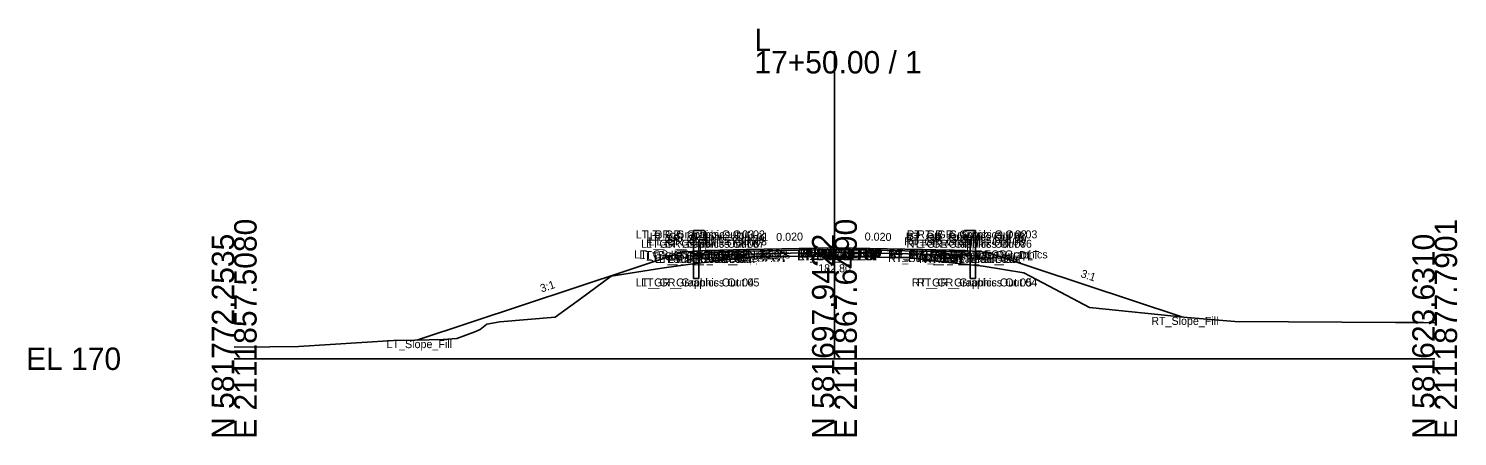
# Model space of a CAD drawing. Extents: x -26 to 3453, y -333 to 9539.
# Drawn here: x -25.7 to 152.8, y 7990.3 to 8041.2 of the extents above; entities that cross this region are included whole.
import ezdxf

# ---------------------------------------------------------------- set-up
doc = ezdxf.new("R2010")
doc.units = 0
for name, color, linetype in [('Default', 7, 'Continuous'), ('Exist Cross Section Cell', 7, 'Continuous'), ('Exist XS Center Line Elevation Label', 7, 'Continuous'), ('Exist XS Ground Line', 7, 'Continuous'), ('Prop CMT Guardrail Graphics', 7, 'Continuous'), ('Prop CMT Pvmt Course 1', 7, 'Continuous'), ('Prop CMT Pvmt Course 2', 7, 'Continuous'), ('Prop CMT Pvmt Course 3', 7, 'Continuous'), ('Prop CMT Pvmt Surface', 7, 'Continuous'), ('Prop CMT Pvmt Surface Shoulder', 7, 'Continuous'), ('Prop CMT Shld Paved Course 1', 7, 'Continuous'), ('Prop CMT Shld Paved Course 2', 7, 'Continuous'), ('Prop CMT Shld Paved Course 3', 7, 'Continuous'), ('Prop CMT Slope Grass', 7, 'Continuous'), ('Prop CMT Subgrade Earthwork', 7, 'Continuous'), ('Prop XS SE Text', 7, 'Continuous'), ('Prop XS Side Slope Text', 7, 'Continuous'), ('Scratch_Level_0', 7, 'Continuous')]:
    doc.layers.add(name, color=color, linetype=linetype)

msp = doc.modelspace()

# ---------------------------------------------------------------- linework, layer by layer
at = {"layer": 'Exist Cross Section Cell'}
for p, q in [((75, 8000), (75, 8038.42)), ((0, 8000), (75, 8000)), ((75, 8000), (150, 8000))]:
    msp.add_line(p, q, dxfattribs=at)
at = {"layer": 'Exist XS Ground Line'}
for p, q in [((57.32, 8011.85), (65.01, 8012.75)), ((65.01, 8012.75), (66.97, 8012.76)), ((66.97, 8012.76), (74.38, 8012.81)), ((74.38, 8012.81), (75, 8012.8)), ((75, 8012.8), (82.19, 8012.66)), ((82.19, 8012.66), (84.29, 8012.63)), ((84.29, 8012.63), (87.35, 8012.21)), ((47.12, 8010.31), (53.43, 8011.3)), ((53.43, 8011.3), (57.32, 8011.85)), ((87.35, 8012.21), (93.59, 8011.58)), ((93.59, 8011.58), (98.65, 8010.74)), ((43.29, 8007.49), (47.12, 8010.31)), ((98.65, 8010.74), (101.82, 8009.05)), ((101.82, 8009.05), (106.87, 8006.41)), ((40.11, 8005.18), (43.29, 8007.49)), ((106.87, 8006.41), (119.06, 8005.16)), ((30.08, 8003.35), (30.73, 8003.64)), ((30.73, 8003.64), (31.58, 8004.32)), ((31.58, 8004.32), (33.18, 8004.63)), ((33.18, 8004.63), (40.11, 8005.18)), ((119.06, 8005.16), (125.03, 8004.66)), ((125.03, 8004.66), (145.1, 8004.52)), ((145.1, 8004.52), (148.61, 8004.51)), ((148.61, 8004.51), (150, 8004.48)), ((8.04, 8001.53), (19.92, 8002.27)), ((19.92, 8002.27), (22.59, 8002.33)), ((22.59, 8002.33), (26.13, 8002.4)), ((26.13, 8002.4), (27.8, 8002.51)), ((27.8, 8002.51), (30.08, 8003.35)), ((0, 8001.51), (0.87, 8001.46)), ((0.87, 8001.46), (8.04, 8001.53))]:
    msp.add_line(p, q, dxfattribs=at)
at = {"layer": 'Prop CMT Guardrail Graphics'}
for points in [[(57.39, 8010.03), (57.39, 8016.03)], [(57.39, 8016.03), (58.72, 8016.03), (58.99, 8015.73)], [(58.99, 8015.15), (58.72, 8014.86), (58.05, 8014.86)], [(58.05, 8014.86), (58.05, 8010.03)], [(58.99, 8015.73), (58.72, 8015.44)], [(58.72, 8015.44), (58.99, 8015.15)], [(92.61, 8016.03), (91.28, 8016.03), (91.01, 8015.73)], [(91.01, 8015.73), (91.28, 8015.44)], [(91.28, 8015.44), (91.01, 8015.15)], [(91.01, 8015.15), (91.28, 8014.86), (91.95, 8014.86)], [(91.95, 8014.86), (91.95, 8010.03)], [(92.61, 8010.03), (92.61, 8016.03)], [(58.05, 8010.03), (57.39, 8010.03)], [(91.95, 8010.03), (92.61, 8010.03)]]:
    msp.add_lwpolyline(points, dxfattribs=at)
at = {"layer": 'Prop CMT Pvmt Course 1'}
for points in [[(75, 8013.85), (64, 8013.63)], [(64, 8013.42), (75, 8013.64)], [(64, 8013.63), (64, 8013.42)], [(75, 8013.64), (75, 8013.85)], [(75, 8013.85), (86, 8013.63)], [(75, 8013.64), (75, 8013.85)], [(86, 8013.42), (75, 8013.64)], [(86, 8013.63), (86, 8013.42)]]:
    msp.add_lwpolyline(points, dxfattribs=at)
msp.add_lwpolyline([(75, 8013.64), (75, 8013.72), (75, 8013.72), (75, 8013.64)], close=True, dxfattribs=at)
msp.add_lwpolyline([(75, 8013.64), (75, 8013.72), (75, 8013.72), (75, 8013.64)], close=True, dxfattribs=at)
at = {"layer": 'Prop CMT Pvmt Course 2'}
for points in [[(75, 8013.64), (64, 8013.42)], [(64, 8013.42), (64, 8013.08)], [(64, 8013.08), (75, 8013.3)], [(75, 8013.3), (75, 8013.64)], [(75, 8013.3), (75, 8013.64)], [(75, 8013.64), (86, 8013.42)], [(86, 8013.08), (75, 8013.3)], [(86, 8013.42), (86, 8013.08)]]:
    msp.add_lwpolyline(points, dxfattribs=at)
at = {"layer": 'Prop CMT Pvmt Course 3'}
for points in [[(75, 8013.3), (64, 8013.08)], [(64, 8013.08), (75, 8013.3)], [(64, 8013.08), (64, 8013.08)], [(75, 8013.3), (75, 8013.3)], [(75, 8013.3), (86, 8013.08)], [(86, 8013.08), (75, 8013.3)], [(75, 8013.3), (75, 8013.3)], [(86, 8013.08), (86, 8013.08)]]:
    msp.add_lwpolyline(points, dxfattribs=at)
at = {"layer": 'Prop CMT Pvmt Surface'}
for points in [[(75, 8013.85), (64, 8013.63)], [(75, 8013.85), (86, 8013.63)]]:
    msp.add_lwpolyline(points, dxfattribs=at)
at = {"layer": 'Prop CMT Pvmt Surface Shoulder'}
for points in [[(64, 8013.63), (59, 8013.53)], [(86, 8013.63), (91, 8013.53)]]:
    msp.add_lwpolyline(points, dxfattribs=at)
at = {"layer": 'Prop CMT Shld Paved Course 1'}
for points in [[(64, 8013.63), (59, 8013.53), (58.79, 8013.31)], [(58.79, 8013.31), (64, 8013.42)], [(64, 8013.42), (64, 8013.63)], [(86, 8013.63), (91, 8013.53), (91.21, 8013.31)], [(86, 8013.42), (86, 8013.63)], [(91.21, 8013.31), (86, 8013.42)]]:
    msp.add_lwpolyline(points, dxfattribs=at)
at = {"layer": 'Prop CMT Shld Paved Course 2'}
for points in [[(64, 8013.42), (58.79, 8013.31), (58.45, 8012.97)], [(58.45, 8012.97), (64, 8013.08)], [(64, 8013.08), (64, 8013.42)], [(86, 8013.42), (91.21, 8013.31), (91.55, 8012.97)], [(86, 8013.08), (86, 8013.42)], [(91.55, 8012.97), (86, 8013.08)]]:
    msp.add_lwpolyline(points, dxfattribs=at)
at = {"layer": 'Prop CMT Shld Paved Course 3'}
for points in [[(64, 8013.08), (58.45, 8012.97)], [(58.45, 8012.97), (64, 8013.08)], [(58.45, 8012.97), (58.45, 8012.97), (58.45, 8012.97)], [(64, 8013.08), (64, 8013.08)], [(86, 8013.08), (91.55, 8012.97)], [(91.55, 8012.97), (86, 8013.08)], [(86, 8013.08), (86, 8013.08)], [(91.55, 8012.97), (91.55, 8012.97), (91.55, 8012.97)]]:
    msp.add_lwpolyline(points, dxfattribs=at)
at = {"layer": 'Prop CMT Slope Grass'}
for points in [[(56, 8013.29), (22.8, 8002.33)], [(58.99, 8013.53), (56, 8013.29)], [(59, 8013.53), (58.99, 8013.53)], [(91, 8013.53), (91.01, 8013.53)], [(91.01, 8013.53), (94, 8013.29)], [(94, 8013.29), (118.41, 8005.23)]]:
    msp.add_lwpolyline(points, dxfattribs=at)
at = {"layer": 'Prop CMT Subgrade Earthwork'}
for points in [[(58.45, 8012.97), (57.98, 8013.44)], [(64, 8013.08), (58.45, 8012.97)], [(75, 8013.3), (64, 8013.08)], [(75, 8013.3), (86, 8013.08)], [(86, 8013.08), (91.55, 8012.97)], [(91.55, 8012.97), (92.02, 8013.44)]]:
    msp.add_lwpolyline(points, dxfattribs=at)

# ---------------------------------------------------------------- texts
at = {"layer": 'Default'}
msp.add_text('-', height=0.0001, dxfattribs=at).set_placement((0, 8000))
at = {"layer": 'Exist Cross Section Cell'}
for s, p in [('L', (65, 8038.42)), ('17+50.00 / 1', (65, 8035.62)), ('EL 170', (-26, 7998.6))]:
    msp.add_text(s, height=2.8, dxfattribs=at).set_placement(p)
for s, p in [('E 2111857.5080', (2.8, 7990)), ('E 2111867.6490', (77.8, 7990)), ('E 2111877.7901', (152.8, 7990)), ('N 581772.2535', (0, 7990)), ('N 581697.9422', (75, 7990)), ('N 581623.6310', (150, 7990))]:
    msp.add_text(s, height=2.8, rotation=90, dxfattribs=at).set_placement(p)
at = {"layer": 'Exist XS Center Line Elevation Label'}
msp.add_text('182.80', height=1, dxfattribs=at).set_placement((72.97, 8010.8))
at = {"layer": 'Prop XS SE Text'}
for rotation, p in [(1.1458, (67.73, 8014.7)), (358.8542, (78.77, 8014.77))]:
    msp.add_text('0.020', height=1, rotation=rotation, dxfattribs=at).set_placement(p)
at = {"layer": 'Prop XS Side Slope Text'}
for rotation, p in [(341.7371, (105.69, 8010.22)), (18.2629, (38.41, 8008.27))]:
    msp.add_text('3:1', height=1, rotation=rotation, dxfattribs=at).set_placement(p)
at = {"layer": 'Scratch_Level_0'}
for s, p in [('LT_GR_Graphics Out 03', (50.17, 8015.03)), ('LT_GR_Graphics Out 06', (50.83, 8013.86)), ('LT_GR_Graphics Out 07', (51.48, 8013.86)), ('LT_GR_Graphics Out 09', (51.49, 8014.44)), ('LT_GR_Graphics Out 02', (51.52, 8015.03)), ('LT_GR_Graphics Out 08', (51.76, 8014.15)), ('LT_GR_Graphics Out 01', (51.94, 8014.73)), ('RT_GR_Graphics Out 08', (83.72, 8014.15)), ('RT_GR_Graphics Out 01', (83.9, 8014.73)), ('RT_GR_Graphics Out 07', (83.98, 8013.86)), ('RT_GR_Graphics Out 09', (84, 8014.44)), ('RT_GR_Graphics Out 02', (84.02, 8015.03)), ('RT_GR_Graphics Out 06', (84.66, 8013.86)), ('RT_GR_Graphics Out 03', (85.34, 8015.03)), ('LT_GS_OS_GR_Face_Graphics', (49.99, 8012.53)), ('LT_Sub_Trench_Out_DLT', (50.63, 8012.44)), ('LT_GS_OS_CTL', (51.46, 8012.29)), ('LT_Sub_Trench_Out', (52.56, 8011.97)), ('LT_PS3_Shelf_Out', (53.1, 8011.97)), ('LT_PS3_OEOP', (54.23, 8011.97)), ('LT_PS2_OEOP', (54.57, 8012.31)), ('LT_PS1_OEOP', (54.91, 8012.53)), ('LT_PV2_OEOT', (59.75, 8012.42)), ('LT_PV3_OEOT', (59.75, 8012.08)), ('LT_Sub_OEOT', (59.77, 8012.08)), ('LT_PV1_OEOT', (59.87, 8012.63)), ('RT_PV2_OEEOP', (70.33, 8012.64)), ('RT_PV3_OEEOP', (70.33, 8012.3)), ('RT_Sub_OEEOP', (70.36, 8012.3)), ('LT_PV2_OEEOP', (70.39, 8012.64)), ('LT_PV3_OEEOP', (70.39, 8012.3)), ('LT_Sub_OEEOP', (70.42, 8012.3)), ('RT_PV1_OEEOP', (70.45, 8012.72)), ('LT_PV1_OEEOP', (70.51, 8012.72)), ('RT_PV2_IEEOP', (70.71, 8012.64)), ('LT_PV2_IEEOP', (70.77, 8012.64)), ('RT_PV1_IEEOP', (70.83, 8012.72)), ('LT_PV1_IEEOP', (70.89, 8012.72)), ('PV2_PGL', (72.35, 8012.64)), ('PV1_PGL', (72.47, 8012.85)), ('RT_PV2_OEOT', (81.69, 8012.42)), ('RT_PV3_OEOT', (81.69, 8012.08)), ('RT_Sub_OEOT', (81.71, 8012.08)), ('RT_PV1_OEOT', (81.81, 8012.63)), ('RT_GS_OS_GR_Face_Graphics', (81.95, 8012.53)), ('RT_Sub_Trench_Out_DLT', (84.61, 8012.44)), ('RT_Sub_Trench_Out', (85.6, 8011.97)), ('RT_PS3_Shelf_Out', (86.15, 8011.97)), ('RT_PS1_OEOP', (86.85, 8012.53)), ('RT_PS2_OEOP', (86.94, 8012.31)), ('RT_PS3_OEOP', (87.28, 8011.97)), ('RT_GS_OS_CTL', (89.4, 8012.29)), ('LT_GR_Graphics Out 04', (50.16, 8009.03)), ('LT_GR_Graphics Out 05', (50.83, 8009.03)), ('RT_GR_Graphics Out 05', (84.67, 8009.03)), ('RT_GR_Graphics Out 04', (85.32, 8009.03)), ('RT_Slope_Fill', (114.59, 8004.23)), ('LT_Slope_Fill', (19.04, 8001.33))]:
    msp.add_text(s, height=1, dxfattribs=at).set_placement(p)

doc.saveas('drawing.dxf')
